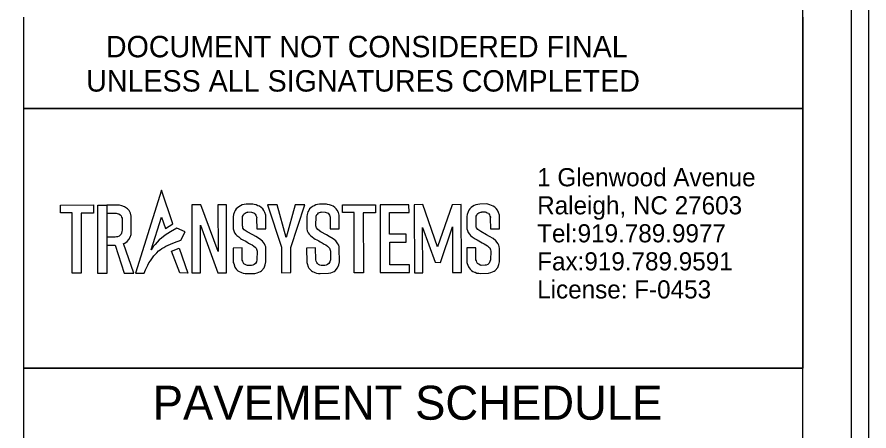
# Model space of a CAD drawing. Extents: x 957297 to 961629, y 830661 to 840840.
# Drawn here: x 960176 to 960394.8, y 839346.6 to 839452.8 of the extents above; entities that cross this region are included whole.
import ezdxf

# ---------------------------------------------------------------- set-up
doc = ezdxf.new("R2010")
doc.units = 0
for name, color, linetype in [('Old_Level_1', 7, 'Continuous'), ('Old_Level_2', 7, 'Continuous'), ('Old_Level_50', 7, 'Continuous'), ('Old_Level_58', 7, 'Continuous'), ('Sheet Plot Border Inside CELL', 7, 'Continuous'), ('Sheet Plot Border Outside CELL', 7, 'Continuous'), ('Sheet Sticker Exception Certification CELL', 7, 'Continuous'), ('Sheet Typical CELL', 7, 'Continuous')]:
    doc.layers.add(name, color=color, linetype=linetype)

# ---------------------------------------------------------------- blocks, each defined once
blk = doc.blocks.new('TSC-LOGO')
at = {"layer": 'Old_Level_1'}
for points in [[(0.1283, 0.107), (0.0949, 0.0004), (0.106, 0.0004), (0.1077, 0.0046), (0.1106, 0.0104), (0.1121, 0.0136), (0.114, 0.0162), (0.1166, 0.02), (0.1183, 0.0224), (0.1202, 0.0243), (0.1221, 0.0263), (0.1245, 0.0288), (0.1266, 0.0301), (0.1286, 0.0318), (0.1314, 0.0334), (0.1339, 0.0348), (0.14, 0.0376), (0.145, 0.0397), (0.1532, 0.0425), (0.1589, 0.0532), (0.148, 0.058), (0.1399, 0.0535), (0.133, 0.049), (0.1281, 0.045), (0.1254, 0.0429), (0.1228, 0.0401), (0.1201, 0.0373), (0.1181, 0.0351), (0.1162, 0.0319), (0.1151, 0.0301), (0.1283, 0.072), (0.1333, 0.0575), (0.1428, 0.0638)], [(-0.0015, 0.0879), (0.0408, 0.0879), (0.0408, 0.0775), (0.0252, 0.0775), (0.0252, 0.0004), (0.0135, 0.0004), (0.0135, 0.078), (-0.0014, 0.078)], [(0.0466, 0.0878), (0.0581, 0.0878), (0.0581, 0), (0.0466, 0)], [(0.0581, 0.0774), (0.0701, 0.0774), (0.0716, 0.0771), (0.0736, 0.0763), (0.0752, 0.0752), (0.0764, 0.0739), (0.0771, 0.0722), (0.0778, 0.0709), (0.0778, 0.068), (0.0778, 0.0556), (0.0775, 0.0539), (0.0771, 0.0517), (0.0764, 0.0503), (0.0754, 0.0489), (0.0741, 0.0479), (0.0719, 0.0471), (0.0703, 0.0469), (0.0687, 0.0467), (0.0581, 0.0467), (0.0582, 0.0361), (0.0687, 0.0362), (0.0805, 0.0003), (0.0926, 0.0005), (0.0794, 0.0382), (0.0813, 0.0388), (0.084, 0.0408), (0.0864, 0.0435), (0.0882, 0.0467), (0.0892, 0.0498), (0.0892, 0.0508), (0.0894, 0.0736), (0.0884, 0.0773), (0.0866, 0.0807), (0.0845, 0.0831), (0.081, 0.0854), (0.0776, 0.0866), (0.0743, 0.0877), (0.0722, 0.0877), (0.0581, 0.0878)], [(0.1671, 0.0879), (0.1671, 0.0006), (0.1783, 0.0006), (0.1783, 0.062), (0.2005, 0.0005), (0.2118, 0.0006), (0.2117, 0.0881), (0.2008, 0.0881), (0.2009, 0.0282), (0.1789, 0.0879)], [(0.2506, 0.057), (0.2621, 0.057), (0.2621, 0.0744), (0.2612, 0.0779), (0.2598, 0.0808), (0.2583, 0.0828), (0.2564, 0.0845), (0.2542, 0.086), (0.2521, 0.0868), (0.2521, 0.0868), (0.2498, 0.0878), (0.2474, 0.0884), (0.2458, 0.0888), (0.237, 0.0886), (0.2344, 0.0882), (0.2321, 0.0878), (0.2298, 0.0866), (0.2278, 0.0855), (0.2258, 0.0841), (0.2243, 0.0826), (0.223, 0.0807), (0.2221, 0.0788), (0.2208, 0.0753), (0.2205, 0.0727), (0.2205, 0.0569), (0.2211, 0.0545), (0.2222, 0.052), (0.2237, 0.05), (0.2252, 0.0484), (0.2274, 0.0467), (0.2297, 0.0449), (0.2311, 0.0438), (0.2335, 0.0427), (0.2359, 0.0416), (0.2379, 0.0403), (0.2401, 0.0389), (0.2427, 0.0375), (0.2449, 0.0364), (0.247, 0.0349), (0.2486, 0.0334), (0.2498, 0.0322), (0.2506, 0.0298), (0.2511, 0.0283), (0.2509, 0.0171), (0.2501, 0.0147), (0.2488, 0.0126), (0.2472, 0.0111), (0.2454, 0.0103), (0.2437, 0.01), (0.2389, 0.0099), (0.2373, 0.0103), (0.2357, 0.0113), (0.234, 0.0123), (0.2333, 0.0139), (0.2326, 0.0156), (0.232, 0.017), (0.2319, 0.0325), (0.2202, 0.0324), (0.2204, 0.0138), (0.221, 0.0124), (0.2223, 0.0081), (0.2232, 0.0067), (0.2244, 0.0051), (0.2263, 0.0032), (0.2279, 0.0022), (0.23, 0.0013), (0.2308, 0.001), (0.233, 0.0001), (0.2357, -0.0002), (0.2376, -0.0004), (0.2483, -0.0001), (0.2513, 0.0006), (0.2554, 0.0024), (0.2568, 0.0031), (0.2599, 0.007), (0.2616, 0.0109), (0.2624, 0.0145), (0.2621, 0.0316), (0.2621, 0.034), (0.2614, 0.0358), (0.2605, 0.0376), (0.2578, 0.0414), (0.2543, 0.0442), (0.2494, 0.0471), (0.2457, 0.0493), (0.2384, 0.0532), (0.2346, 0.056), (0.2329, 0.0581), (0.2326, 0.0595), (0.2322, 0.0609), (0.2324, 0.0731), (0.233, 0.0744), (0.2337, 0.0756), (0.2346, 0.0764), (0.2357, 0.0774), (0.237, 0.0779), (0.2383, 0.0784), (0.239, 0.0783), (0.2391, 0.0787), (0.2439, 0.0786), (0.2453, 0.078), (0.2467, 0.0775), (0.2481, 0.0769), (0.2487, 0.076), (0.2496, 0.0746), (0.2501, 0.0732), (0.2506, 0.0718), (0.2505, 0.0703)], [(0.277, 0.0878), (0.2643, 0.0878), (0.2823, 0.0334), (0.2825, 0.0007), (0.2944, 0.0008), (0.2943, 0.0332), (0.3126, 0.088), (0.3001, 0.0877), (0.2886, 0.046)], [(0.3449, 0.057), (0.3565, 0.057), (0.3565, 0.0744), (0.3555, 0.0779), (0.3541, 0.0808), (0.3526, 0.0828), (0.3508, 0.0845), (0.3486, 0.086), (0.3465, 0.0868), (0.3465, 0.0868), (0.3442, 0.0878), (0.3417, 0.0884), (0.3401, 0.0888), (0.3314, 0.0886), (0.3288, 0.0882), (0.3265, 0.0878), (0.3242, 0.0866), (0.3221, 0.0855), (0.3202, 0.0841), (0.3186, 0.0826), (0.3174, 0.0807), (0.3164, 0.0788), (0.3152, 0.0753), (0.3149, 0.0727), (0.3149, 0.0569), (0.3155, 0.0545), (0.3166, 0.052), (0.318, 0.05), (0.3195, 0.0484), (0.3218, 0.0467), (0.324, 0.0449), (0.3255, 0.0438), (0.3279, 0.0427), (0.3303, 0.0416), (0.3322, 0.0403), (0.3344, 0.0389), (0.3371, 0.0375), (0.3392, 0.0364), (0.3414, 0.0349), (0.3429, 0.0334), (0.3442, 0.0322), (0.3449, 0.0298), (0.3454, 0.0283), (0.3452, 0.0171), (0.3444, 0.0147), (0.3432, 0.0126), (0.3416, 0.0111), (0.3398, 0.0103), (0.3381, 0.01), (0.3333, 0.0099), (0.3317, 0.0103), (0.33, 0.0113), (0.3284, 0.0123), (0.3277, 0.0139), (0.327, 0.0156), (0.3264, 0.017), (0.3262, 0.0325), (0.3145, 0.0324), (0.3147, 0.0138), (0.3153, 0.0124), (0.3167, 0.0081), (0.3175, 0.0067), (0.3188, 0.0051), (0.3207, 0.0032), (0.3222, 0.0022), (0.3244, 0.0013), (0.3252, 0.001), (0.3273, 0.0001), (0.33, -0.0002), (0.332, -0.0004), (0.3427, -0.0001), (0.3457, 0.0006), (0.3498, 0.0024), (0.3512, 0.0031), (0.3543, 0.007), (0.356, 0.0109), (0.3567, 0.0145), (0.3565, 0.0316), (0.3565, 0.034), (0.3558, 0.0358), (0.3549, 0.0376), (0.3522, 0.0414), (0.3486, 0.0442), (0.3438, 0.0471), (0.34, 0.0493), (0.3327, 0.0532), (0.3289, 0.056), (0.3273, 0.0581), (0.3269, 0.0595), (0.3265, 0.0609), (0.3268, 0.0731), (0.3274, 0.0744), (0.328, 0.0756), (0.3289, 0.0764), (0.3301, 0.0774), (0.3314, 0.0779), (0.3327, 0.0784), (0.3334, 0.0783), (0.3335, 0.0787), (0.3383, 0.0786), (0.3396, 0.078), (0.341, 0.0775), (0.3424, 0.0769), (0.3431, 0.076), (0.344, 0.0746), (0.3445, 0.0732), (0.3449, 0.0718), (0.3449, 0.0703)], [(0.3608, 0.0879), (0.4031, 0.0879), (0.4031, 0.0775), (0.3875, 0.0775), (0.3875, 0.0004), (0.3758, 0.0004), (0.3758, 0.078), (0.3609, 0.078)], [(0.4461, 0.0878), (0.4092, 0.0878), (0.4092, 0.0007), (0.4466, 0.0007), (0.4466, 0.0106), (0.4213, 0.0106), (0.4213, 0.0398), (0.4424, 0.0398), (0.4424, 0.0502), (0.4211, 0.0502), (0.4211, 0.0777), (0.4462, 0.0777)], [(0.4829, 0.0336), (0.4639, 0.0882), (0.4529, 0.0877), (0.4532, 0.0004), (0.4638, 0.0004), (0.4635, 0.0588), (0.4798, 0.0139), (0.4866, 0.0137), (0.502, 0.0593), (0.5021, 0.0007), (0.5135, 0.0008), (0.5133, 0.0879), (0.5018, 0.0878)], [(0.5506, 0.057), (0.5622, 0.057), (0.5622, 0.0744), (0.5612, 0.0779), (0.5598, 0.0808), (0.5583, 0.0828), (0.5564, 0.0845), (0.5542, 0.086), (0.5521, 0.0868), (0.5521, 0.0868), (0.5498, 0.0878), (0.5474, 0.0884), (0.5458, 0.0888), (0.5371, 0.0886), (0.5344, 0.0882), (0.5321, 0.0878), (0.5298, 0.0866), (0.5278, 0.0855), (0.5258, 0.0841), (0.5243, 0.0826), (0.5231, 0.0807), (0.5221, 0.0788), (0.5208, 0.0753), (0.5206, 0.0727), (0.5205, 0.0569), (0.5211, 0.0545), (0.5223, 0.052), (0.5237, 0.05), (0.5252, 0.0484), (0.5274, 0.0467), (0.5297, 0.0449), (0.5311, 0.0438), (0.5335, 0.0427), (0.5359, 0.0416), (0.5379, 0.0403), (0.5401, 0.0389), (0.5427, 0.0375), (0.5449, 0.0364), (0.5471, 0.0349), (0.5486, 0.0334), (0.5499, 0.0322), (0.5506, 0.0298), (0.5511, 0.0283), (0.5509, 0.0171), (0.5501, 0.0147), (0.5489, 0.0126), (0.5472, 0.0111), (0.5454, 0.0103), (0.5437, 0.01), (0.5389, 0.0099), (0.5373, 0.0103), (0.5357, 0.0113), (0.534, 0.0123), (0.5333, 0.0139), (0.5326, 0.0156), (0.5321, 0.017), (0.5319, 0.0325), (0.5202, 0.0324), (0.5204, 0.0138), (0.521, 0.0124), (0.5223, 0.0081), (0.5232, 0.0067), (0.5245, 0.0051), (0.5264, 0.0032), (0.5279, 0.0022), (0.5301, 0.0013), (0.5309, 0.001), (0.533, 0.0001), (0.5357, -0.0002), (0.5376, -0.0004), (0.5483, -0.0001), (0.5513, 0.0006), (0.5554, 0.0024), (0.5568, 0.0031), (0.56, 0.007), (0.5616, 0.0109), (0.5624, 0.0145), (0.5622, 0.0316), (0.5621, 0.034), (0.5615, 0.0358), (0.5605, 0.0376), (0.5578, 0.0414), (0.5543, 0.0442), (0.5494, 0.0471), (0.5457, 0.0493), (0.5384, 0.0532), (0.5346, 0.056), (0.533, 0.0581), (0.5326, 0.0595), (0.5322, 0.0609), (0.5324, 0.0731), (0.5331, 0.0744), (0.5337, 0.0756), (0.5346, 0.0764), (0.5357, 0.0774), (0.537, 0.0779), (0.5383, 0.0784), (0.5391, 0.0783), (0.5391, 0.0787), (0.5439, 0.0786), (0.5453, 0.078), (0.5467, 0.0775), (0.5481, 0.0769), (0.5487, 0.076), (0.5497, 0.0746), (0.5501, 0.0732), (0.5506, 0.0718), (0.5505, 0.0703)], [(0.1413, 0.0285), (0.1509, 0.0323), (0.1622, 0.0001), (0.1517, 0.0005)]]:
    blk.add_lwpolyline(points, close=True, dxfattribs=at)
blk = doc.blocks.new('TRANSYSTEMS Logo')
at = {"layer": 'Old_Level_58'}
blk.add_lwpolyline([(0, 66.69), (200.05, 66.69), (200.05, 0), (0, 0)], close=True, dxfattribs=at)
at = {"layer": 'Old_Level_1', "xscale": 199.99999999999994, "yscale": 199.99999999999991, "rotation": 0.05340743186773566}
blk.add_blockref('TSC-LOGO', (9.71, 24.35), dxfattribs=at)
at = {"layer": 'Old_Level_2'}
for s, p in [('1 Glenwood Avenue', (131.85, 46.73)), ('Raleigh, NC 27603', (131.85, 39.53)), ('Tel:919.789.9977 ', (131.85, 32.34)), ('Fax:919.789.9591', (131.85, 25.14)), ('License: F-0453', (131.85, 17.94))]:
    blk.add_text(s, height=4.6576, rotation=360, dxfattribs=at).set_placement(p)

msp = doc.modelspace()

# ---------------------------------------------------------------- linework, layer by layer
at = {"layer": 'Old_Level_50'}
for p, q in [((960177.75, 839012.44), (960177.75, 839362.65)), ((960177.76, 839362.65), (960377.8, 839362.65))]:
    msp.add_line(p, q, dxfattribs=at)
at = {"layer": 'Sheet Plot Border Inside CELL'}
msp.add_lwpolyline([(960390.3, 839592.94), (958723.8, 839592.94), (958723.8, 838537.84), (960390.3, 838537.84)], close=True, dxfattribs=at)
at = {"layer": 'Sheet Plot Border Outside CELL'}
msp.add_lwpolyline([(960394.8, 839615.39), (958710.8, 839615.39), (958710.8, 838515.39), (960394.8, 838515.39)], close=True, dxfattribs=at)
at = {"layer": 'Sheet Sticker Exception Certification CELL'}
for p, q in [((960177.75, 839429.34), (960177.75, 839452.84)), ((960377.79, 839452.83), (960377.79, 839429.33)), ((960377.79, 839429.34), (960177.75, 839429.34))]:
    msp.add_line(p, q, dxfattribs=at)
at = {"layer": 'Sheet Typical CELL'}
msp.add_lwpolyline([(960377.8, 839590.39), (958877.8, 839590.39), (958877.8, 838540.39), (960377.8, 838540.39)], close=True, dxfattribs=at)

# ---------------------------------------------------------------- block references
at = {"layer": 'Old_Level_2'}
msp.add_blockref('TRANSYSTEMS Logo', (960177.74, 839362.65), dxfattribs=at)

# ---------------------------------------------------------------- texts
at = {"layer": 'Old_Level_50'}
msp.add_text('PAVEMENT SCHEDULE', height=8.7206, dxfattribs=at).set_placement((960210.85, 839349.46))
at = {"layer": 'Sheet Sticker Exception Certification CELL'}
for s, p in [('DOCUMENT NOT CONSIDERED FINAL', (960198.82, 839442.5)), ('UNLESS ALL SIGNATURES COMPLETED', (960193.75, 839433.7))]:
    msp.add_text(s, height=5.5, dxfattribs=at).set_placement(p)

doc.saveas('drawing.dxf')
